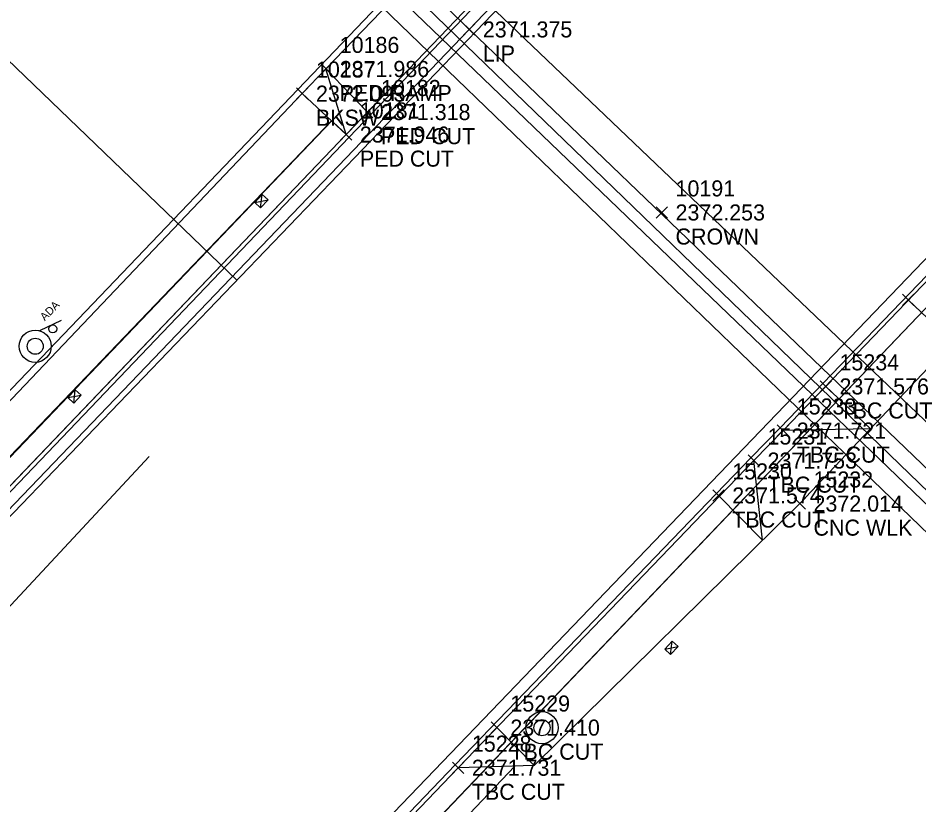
# Model space of a CAD drawing. Extents: x 2377639 to 2379738, y 729875 to 732734.
# Drawn here: x 2378410.6 to 2378522.8, y 730622.6 to 730720.7 of the extents above; entities that cross this region are included whole.
import ezdxf

# ---------------------------------------------------------------- set-up
doc = ezdxf.new("R2010")
doc.units = 0
for name, color, linetype in [('Default', 7, 'Continuous'), ('TOPO_CURBGTR_Back-of-Curb', 7, 'Continuous'), ('TOPO_CURBGTR_Face-of-Curb', 7, 'Continuous'), ('TOPO_CURBGTR_Lip-of-Gutter', 7, 'Continuous'), ('TOPO_DATA_Elevations', 7, 'Continuous'), ('TOPO_DATA_Notes', 7, 'Continuous'), ('TOPO_ELEC_Cable_Overhead-Exist', 7, 'Continuous'), ('TOPO_MISC_Flat-Asphalt', 7, 'Continuous'), ('TOPO_SAN_Plastic-Pipe', 7, 'Continuous'), ('TOPO_SAN_Sewer-Manhole', 7, 'Continuous'), ('TOPO_SIGNS_Post-Single', 7, 'Continuous'), ('TOPO_STORM_Line-Other', 7, 'Continuous'), ('TOPO_SW_Back', 7, 'Continuous'), ('TOPO_TELE_Overhead-Line', 7, 'Continuous'), ('TOPO_TV_Cable-Overhead', 7, 'Continuous'), ('TOPO_WTRUTIL_Irrig-Box', 7, 'Continuous'), ('TOPO_WTRUTIL_Line', 7, 'Continuous')]:
    doc.layers.add(name, color=color, linetype=linetype)

# ---------------------------------------------------------------- blocks, each defined once
blk = doc.blocks.new('SIGN_6')
at = {"layer": 'Default'}
blk.add_line((0.0064, 0.0197), (0.0064, -0.0185), dxfattribs=at)
blk.add_circle((0, 0), 0.00635, dxfattribs=at)
blk = doc.blocks.new('SPRBOX_5')
at = {"layer": 'Default'}
for p, q in [((-0.0086, -0.0064), (0.0086, 0.0064)), ((-0.0086, 0.0064), (0.0086, -0.0064)), ((-0.0086, 0.0064), (0.0086, 0.0064)), ((-0.0086, 0.0064), (-0.0086, -0.0064)), ((0.0086, 0.0064), (0.0086, -0.0064)), ((-0.0086, -0.0064), (0.0086, -0.0064))]:
    blk.add_line(p, q, dxfattribs=at)
blk = doc.blocks.new('MH_16')
at = {"layer": 'Default'}
for radius in [0.0254, 0.0127]:
    blk.add_circle((0, 0), radius, dxfattribs=at)

msp = doc.modelspace()

# ---------------------------------------------------------------- linework, layer by layer
at = {"layer": 'TOPO_CURBGTR_Back-of-Curb'}
for points in [[(2378796.95, 731066.54), (2378792.22, 731061.65), (2378780.11, 731049.06), (2378765.8, 731034.16), (2378729.83, 730996.57), (2378708.78, 730974.71), (2378675.54, 730940.1), (2378596.07, 730857.01), (2378571.8, 730831.72), (2378484.65, 730740.78), (2378451.54, 730706.2), (2378383.47, 730635.07)], [(2378428.64, 730588.82), (2378465.5, 730627.29), (2378502.36, 730665.57), (2378506, 730669.31), (2378527.48, 730691.63), (2378605.98, 730773.58), (2378608.94, 730776.83)]]:
    msp.add_lwpolyline(points, dxfattribs=at)
at = {"layer": 'TOPO_CURBGTR_Face-of-Curb'}
for points in [[(2378797.32, 731066.2), (2378792.58, 731061.31), (2378780.47, 731048.72), (2378766.16, 731033.81), (2378730.19, 730996.23), (2378709.14, 730974.36), (2378675.9, 730939.76), (2378596.44, 730856.66), (2378572.16, 730831.38), (2378485.01, 730740.44), (2378451.9, 730705.86), (2378383.83, 730634.72)], [(2378428.28, 730589.17), (2378465.14, 730627.64), (2378502, 730665.92), (2378505.64, 730669.66), (2378527.12, 730691.97), (2378605.61, 730773.92), (2378608.57, 730777.17)]]:
    msp.add_lwpolyline(points, dxfattribs=at)
at = {"layer": 'TOPO_CURBGTR_Lip-of-Gutter'}
for points in [[(2378797.98, 731065.07), (2378794.67, 731061.59), (2378781.68, 731047.95), (2378751.07, 731015.98), (2378690.75, 730953), (2378584.09, 730841.86), (2378466.86, 730719.3), (2378390.08, 730639.26), (2378384.85, 730633.62), (2378384.85, 730633.62)], [(2378609, 730779.64), (2378604.75, 730775.02), (2378431.05, 730594.21), (2378426.07, 730588.91)]]:
    msp.add_lwpolyline(points, dxfattribs=at)
at = {"layer": 'TOPO_DATA_Elevations'}
for p, q in [((2378466.16, 730718.6), (2378467.57, 730720.01)), ((2378466.16, 730720.01), (2378467.57, 730718.6)), ((2378448.32, 730713.67), (2378449.73, 730715.08)), ((2378448.32, 730715.08), (2378449.73, 730713.67)), ((2378445.36, 730710.59), (2378446.77, 730712.01)), ((2378445.36, 730712.01), (2378446.77, 730710.59)), ((2378453.47, 730708.29), (2378454.88, 730709.71)), ((2378453.47, 730709.71), (2378454.88, 730708.29)), ((2378450.83, 730705.49), (2378452.24, 730706.91)), ((2378450.83, 730706.91), (2378452.24, 730705.49)), ((2378490.18, 730695.78), (2378491.6, 730697.2)), ((2378490.18, 730697.2), (2378491.6, 730695.78)), ((2378520.89, 730684.88), (2378522.3, 730686.29)), ((2378520.89, 730686.29), (2378522.3, 730684.88)), ((2378510.62, 730674.1), (2378512.04, 730675.51)), ((2378510.62, 730675.51), (2378512.04, 730674.1)), ((2378505.29, 730668.61), (2378506.71, 730670.02)), ((2378505.29, 730670.02), (2378506.71, 730668.61)), ((2378501.65, 730664.87), (2378503.07, 730666.28)), ((2378501.65, 730666.28), (2378503.07, 730664.87)), ((2378497.26, 730660.52), (2378498.67, 730661.93)), ((2378497.26, 730661.93), (2378498.67, 730660.52)), ((2378507.38, 730659.51), (2378508.8, 730660.92)), ((2378507.38, 730660.92), (2378508.8, 730659.51)), ((2378469.6, 730631.58), (2378471.01, 730632.99)), ((2378469.6, 730632.99), (2378471.01, 730631.58)), ((2378464.79, 730626.59), (2378466.21, 730628)), ((2378464.79, 730628), (2378466.21, 730626.59))]:
    msp.add_line(p, q, dxfattribs=at)
at = {"layer": 'TOPO_ELEC_Cable_Overhead-Exist'}
for p in [(2378314.05, 730574.41), (2378553.19, 730631.94)]:
    msp.add_line(p, (2378457.25, 730724.11), dxfattribs=at)
at = {"layer": 'TOPO_MISC_Flat-Asphalt'}
msp.add_lwpolyline([(2378386.73, 730642.11), (2378449.73, 730707.92), (2378451.54, 730706.2), (2378388.53, 730640.39)], close=True, dxfattribs=at)
at = {"layer": 'TOPO_SAN_Plastic-Pipe'}
msp.add_line((2378737.85, 730466.14), (2378460.89, 730730.47), dxfattribs=at)
at = {"layer": 'TOPO_STORM_Line-Other'}
for q in [(2378187, 730332.08), (2378188.38, 730333.53)]:
    msp.add_line((2378608.31, 730773.03), q, dxfattribs=at)
at = {"layer": 'TOPO_SW_Back'}
msp.add_line((2378451.54, 730706.2), (2378446.06, 730711.3), dxfattribs=at)
for points in [[(2378474.98, 730627.55), (2378508.09, 730660.21), (2378532.77, 730686.32), (2378606.65, 730763.63), (2378611.23, 730768.23), (2378618.35, 730761.5)], [(2378449.02, 730714.37), (2378460.46, 730726.31), (2378476.31, 730743.06), (2378484.65, 730740.78)], [(2378397.74, 730660.6), (2378446.06, 730711.3), (2378449.02, 730714.37)], [(2378451.54, 730706.2), (2378449.02, 730714.37), (2378454.2, 730708.98)], [(2378388.54, 730640.37), (2378386.73, 730642.11), (2378394.23, 730650.07), (2378449.71, 730707.91)], [(2378521.63, 730685.55), (2378527.13, 730680.36), (2378527.48, 730691.63)], [(2378511.31, 730674.83), (2378516.9, 730669.54), (2378506, 730669.31)], [(2378497.96, 730661.22), (2378503.46, 730655.65), (2378502.36, 730665.57)], [(2378470.31, 730632.29), (2378474.98, 730627.55), (2378465.5, 730627.29)], [(2378472.57, 730627.49), (2378437.01, 730590.1), (2378437.22, 730583.52), (2378437.08, 730581.81), (2378436.42, 730582.29), (2378433.85, 730578.9), (2378437.48, 730575.6), (2378436.95, 730564.08), (2378444.09, 730557.19)]]:
    msp.add_lwpolyline(points, dxfattribs=at)
at = {"layer": 'TOPO_TELE_Overhead-Line'}
for p, q in [((2378751.05, 730446.34), (2378268.25, 730910.16)), ((2378564.13, 730622.97), (2378353.69, 730826.29))]:
    msp.add_line(p, q, dxfattribs=at)
at = {"layer": 'TOPO_TV_Cable-Overhead'}
msp.add_line((2378746.7, 730441.54), (2378265.21, 730906.27), dxfattribs=at)
at = {"layer": 'TOPO_WTRUTIL_Line'}
for p, q in [((2378391.81, 730640.09), (2378830.45, 731096.49)), ((2378409.26, 730715.61), (2378437.92, 730688.07)), ((2378324.98, 730556.57), (2378426.96, 730666.08))]:
    msp.add_line(p, q, dxfattribs=at)

# ---------------------------------------------------------------- block references
at = {"layer": 'TOPO_SAN_Sewer-Manhole', "xscale": 78.74000000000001, "yscale": 78.74000000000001}
for p in [(2378412.77, 730679.81), (2378475.95, 730632.28)]:
    msp.add_blockref('MH_16', p, dxfattribs=at)
at = {"layer": 'TOPO_SIGNS_Post-Single', "xscale": 78.73999999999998, "yscale": 78.74000000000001, "rotation": 115.3536896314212}
msp.add_blockref('SIGN_6', (2378414.96, 730681.98), dxfattribs=at)
at = {"layer": 'TOPO_WTRUTIL_Irrig-Box', "xscale": 78.74000000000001, "yscale": 78.74, "rotation": 46.80140440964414}
for p in [(2378440.97, 730697.9), (2378417.67, 730673.56), (2378492.08, 730642.23)]:
    msp.add_blockref('SPRBOX_5', p, dxfattribs=at)

# ---------------------------------------------------------------- texts
at = {"layer": 'TOPO_DATA_Elevations'}
for s, p in [('2371.375', (2378468.57, 730718.3)), ('10186', (2378450.73, 730716.37)), ('LIP', (2378468.57, 730715.3)), ('10187', (2378447.77, 730713.3)), ('2371.986', (2378450.73, 730713.37)), ('2372.093', (2378447.77, 730710.3)), ('PED RAMP', (2378450.73, 730710.37)), ('10182', (2378455.88, 730711)), ('10181', (2378453.24, 730708.2)), ('2371.318', (2378455.88, 730708)), ('BKSW', (2378447.77, 730707.3)), ('2371.946', (2378453.24, 730705.2)), ('PED CUT', (2378455.88, 730705)), ('PED CUT', (2378453.24, 730702.2)), ('10191', (2378492.6, 730698.49)), ('2372.253', (2378492.6, 730695.49)), ('CROWN', (2378492.6, 730692.49)), ('15234', (2378513.04, 730676.81)), ('2371.576', (2378513.04, 730673.81)), ('15233', (2378507.71, 730671.31)), ('TBC CUT', (2378513.04, 730670.81)), ('15231', (2378504.07, 730667.57)), ('2371.721', (2378507.71, 730668.31)), ('TBC CUT', (2378507.71, 730665.31)), ('2371.753', (2378504.07, 730664.57)), ('15230', (2378499.67, 730663.22)), ('15232', (2378509.8, 730662.21)), ('TBC CUT', (2378504.07, 730661.57)), ('2371.574', (2378499.67, 730660.22)), ('2372.014', (2378509.8, 730659.21)), ('TBC CUT', (2378499.67, 730657.22)), ('CNC WLK', (2378509.8, 730656.21)), ('15229', (2378472.01, 730634.29)), ('2371.410', (2378472.01, 730631.29)), ('15228', (2378467.21, 730629.29)), ('TBC CUT', (2378472.01, 730628.29)), ('2371.731', (2378467.21, 730626.29)), ('TBC CUT', (2378467.21, 730623.29))]:
    msp.add_text(s, height=2, dxfattribs=at).set_placement(p)
at = {"layer": 'TOPO_DATA_Notes'}
msp.add_text('ADA', height=1, rotation=45.6392, dxfattribs=at).set_placement((2378413.97, 730682.91))

doc.saveas('drawing.dxf')
